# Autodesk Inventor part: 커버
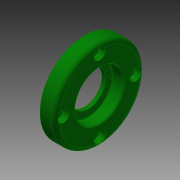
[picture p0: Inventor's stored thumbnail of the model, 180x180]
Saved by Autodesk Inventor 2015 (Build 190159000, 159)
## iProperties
Created: 2018-11
Part Number: 커버
Material: 알루미늄 6061
Document SubType Name: Modeling
Designer: mduedu
Density: 1 g/cm^3
Appearance: 진녹색
Author: mduedu
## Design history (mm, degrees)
revolve "회전1" stored, may be unused: angle "d7" = 90 deg
revolve "회전2" stored, may be unused: angle "d14" = 90 deg
fillet "모깎기1" dims "d15" = 0.3
chamfer "모따기1" distance "d16" = 0.8; stored, may be unused: second distance "d17" = 2, angle "d18" = 30 deg
fillet "모깎기2" dims "d19" = 1, "d35" = 3
chamfer "모따기2" distance "d20" = 0.5; stored, may be unused: second distance "d21" = 2, angle "d22" = 30 deg
sketch "스케치5" dims "d55" = 60
  geometry: 3 further points
  constraints: 2 vertical alignment, 1 coincident, 2 other
hole "구멍3" sketch "스케치5" at (0, 30) diameter "d56" = 4.5; stored, may be unused: countersink angle "d60" = 90 deg, drill point angle "d62" = 118 deg; dims "d57" = 6, "d58" = 8, "d59" = 4.4, "d61" = 8
node "솔리드1"
pattern_circular "원형 패턴1" dims angle "d64" = 360 deg
sketch "스케치1"
  geometry: L1 (0, 0)-(3, 0); L2 (3, 23.5)-(0, 23.5); L3 (0, 23.5)-(0, 0); L4 (3, 0)-(9, 0); L5 (11, 38)-(3, 38); L6 (3, 38)-(3, 23.5); L7 (9, 0)-(14, 0); L8 (14, 0)-(14, 35); A1 r 3 centre (11, 35) between (14, 35) and (11, 38)
  constraints: 16 end point, 3 horizontal, 2 parallel, 2 point on circle, 2 tangent, 1 centre point, 1 perpendicular, 1 vertical
  dimensions: "d0" = 76 diameter of L5 L4; "d3" = 47 diameter of L2 L1; "d6" = 14 distance between parallel lines of L8 L3; "d46" = 3 distance between parallel lines of L6 L3; "d47" = 3 radius of A1
sketch "스케치2"
  geometry: L1 (0, -23.5)-(0, 23.5) reference; L2 (0, 23.5)-(3, 23.5) reference; L3 (3, 23.5)-(3, 38) reference; L4 (3, 38)-(11, 38) reference; L5 (11, -38)-(3, -38) reference; L6 (3, -38)-(3, -23.5) reference; L7 (3, -23.5)-(0, -23.5) reference; L8 (0, 0)-(3, 0); L9 (3, 0)-(3, 20); L10 (3, 20)-(0, 20); L11 (0, 20)-(0, 0); L12 (3, 0)-(5.7, 0); L13 (5.7, 0)-(5.7, 12.5); L14 (5.7, 12.5)-(3, 12.5); L15 (3, 12.5)-(3, 0); L16 (5.7, 0)-(14, 0); L17 (14, 0)-(14, 17.5); L18 (14, 17.5)-(5.7, 17.5); L19 (5.7, 17.5)-(5.7, 0); L20 (14, 35)-(14, -35) reference; A1 r 3 centre (11, 35) between (14, 35) and (11, 38) reference; A2 r 3 centre (11, -35) between (11, -38) and (14, -35) reference
  constraints: 24 end point, 6 parallel, 3 horizontal, 3 perpendicular
  dimensions: "d8" = 35 diameter of L18 L16; "d10" = 25 diameter of L14 L12; "d11" = 40 diameter of L10 L8; "d12" = 3 distance of L9.end L10.end; "d13" = 8.3 distance of L17.end L18.end
node "절단 모서리 투영1"
